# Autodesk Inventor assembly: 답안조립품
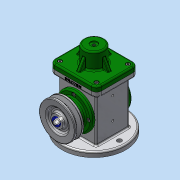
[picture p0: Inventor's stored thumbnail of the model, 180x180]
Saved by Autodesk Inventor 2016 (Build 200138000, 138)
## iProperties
Created: 2018-10
Part Number: 답안조립품
Material: 일반
Document SubType Name: Assembly
Designer: Administrator
Author: Administrator
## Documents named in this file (18)
- C:\Users\Administrator\Desktop\481007V1062\답안조립품.iam
- C:\Users\Administrator\Desktop\481007V1062\본체.ipt
- C:\Users\Administrator\Desktop\481007V1062\편심축.ipt
- C:\Users\Administrator\Desktop\481007V1062\뒤커버.ipt
- C:\Users\Administrator\Desktop\481007V1062\베어링 17 x 40 x 12.ipt
- C:\Users\Administrator\Desktop\481007V1062\볼트 M4 x 8.ipt
- C:\Users\Administrator\Desktop\481007V1062\앞커버.ipt
- C:\Users\Administrator\Desktop\481007V1062\오일 실 17 30 8.ipt
- C:\Users\Administrator\Desktop\481007V1062\키 4 x 4 x 12.ipt
- C:\Users\Administrator\Desktop\481007V1062\V-벨트풀리.ipt
- C:\Users\Administrator\Desktop\481007V1062\와셔 4x16.ipt
- C:\Users\Administrator\Desktop\481007V1062\볼트 M4 x 10.ipt
- C:\Users\Administrator\Desktop\481007V1062\링크.ipt
- C:\Users\Administrator\Desktop\481007V1062\슬라이더.ipt
- C:\Users\Administrator\Desktop\481007V1062\클레비스 핀 6 x 22.ipt
- 클레비스 핀 6 x 22.ipt
- C:\Users\Administrator\Desktop\481007V1062\E-링.ipt
- C:\Users\Administrator\Desktop\481007V1062\덮개.ipt
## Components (2 placed, 2 different names)
1. V-벨트풀리:1
2. E-링:1
